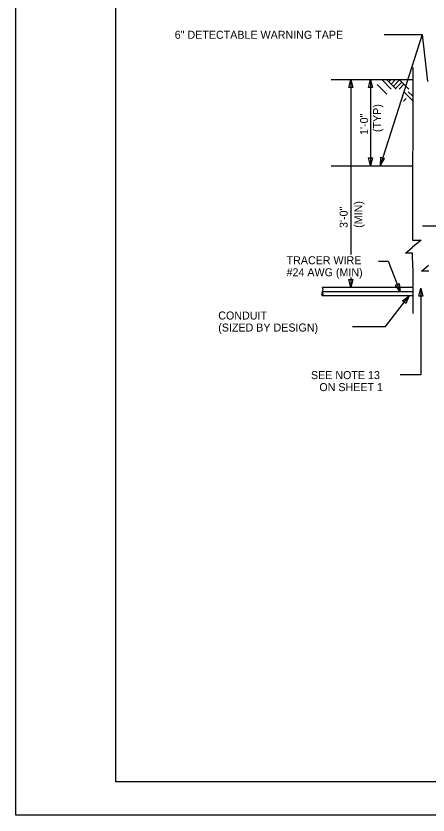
# Model space of a CAD drawing. Extents: x 1299104.8 to 1299141.6, y 239639.8 to 239661.8.
# Drawn here: x 1299104.8 to 1299110.98, y 239639.8 to 239651.78 of the extents above; entities that cross this region are included whole.
import ezdxf

# ---------------------------------------------------------------- set-up
doc = ezdxf.new("R2010")
doc.units = 0
for name, color, linetype in [('DIM TXT', 7, 'Continuous'), ('GS_plotshape_p', 7, 'Continuous'), ('Level 1', 7, 'Continuous')]:
    doc.layers.add(name, color=color, linetype=linetype)

msp = doc.modelspace()

# ---------------------------------------------------------------- linework, layer by layer
at = {"layer": 'DIM TXT'}
for p, q in [((1299110.897, 239651.5), (1299110.266, 239649.532)), ((1299110.755, 239651.005), (1299110.752, 239648.496)), ((1299109.532, 239650.823), (1299110.753, 239650.823)), ((1299109.825, 239650.823), (1299109.825, 239648.201)), ((1299110.123, 239650.823), (1299110.123, 239649.532)), ((1299110.433, 239650.68), (1299110.289, 239650.823)), ((1299110.504, 239650.681), (1299110.36, 239650.823)), ((1299110.429, 239650.823), (1299110.395, 239650.789)), ((1299110.497, 239650.823), (1299110.429, 239650.755)), ((1299110.558, 239650.818), (1299110.462, 239650.721)), ((1299110.696, 239650.681), (1299110.553, 239650.823)), ((1299110.366, 239650.602), (1299110.22, 239650.747)), ((1299110.593, 239650.783), (1299110.498, 239650.687)), ((1299110.623, 239650.754), (1299110.551, 239650.681)), ((1299110.753, 239650.509), (1299110.621, 239650.641)), ((1299110.754, 239650.573), (1299110.685, 239650.641)), ((1299110.657, 239650.538), (1299110.616, 239650.497)), ((1299109.532, 239649.532), (1299110.753, 239649.532)), ((1299110.752, 239648.678), (1299110.753, 239648.417)), ((1299120.075, 239648.627), (1299110.902, 239648.627)), ((1299110.753, 239648.417), (1299110.879, 239648.417)), ((1299110.879, 239648.417), (1299110.753, 239648.313)), ((1299110.644, 239648.222), (1299110.753, 239648.313)), ((1299110.753, 239648.222), (1299110.644, 239648.222)), ((1299110.754, 239648.004), (1299110.753, 239648.222)), ((1299110.754, 239648.004), (1299110.754, 239647.318)), ((1299110.885, 239647.952), (1299110.994, 239648.042)), ((1299110.995, 239647.952), (1299110.885, 239647.952)), ((1299109.825, 239647.858), (1299109.825, 239647.704)), ((1299110.754, 239647.706), (1299109.399, 239647.706)), ((1299110.754, 239647.642), (1299109.399, 239647.642)), ((1299110.754, 239647.581), (1299109.399, 239647.581))]:
    msp.add_line(p, q, dxfattribs=at)
for points in [[(1299110.325, 239651.5), (1299110.897, 239651.5), (1299110.976, 239650.793)], [(1299110.24, 239648.103), (1299110.385, 239648.103), (1299110.568, 239647.642)], [(1299110.874, 239647.698), (1299110.874, 239646.4), (1299110.564, 239646.4)], [(1299109.853, 239647.121), (1299110.347, 239647.121), (1299110.701, 239647.581)]]:
    msp.add_lwpolyline(points, dxfattribs=at)
for points in [[(1299109.797, 239650.705), (1299109.826, 239650.825), (1299109.857, 239650.706)], [(1299110.093, 239650.705), (1299110.122, 239650.825), (1299110.153, 239650.706)], [(1299110.152, 239649.652), (1299110.123, 239649.532), (1299110.092, 239649.652)], [(1299110.272, 239649.655), (1299110.266, 239649.532), (1299110.33, 239649.638)], [(1299109.854, 239647.827), (1299109.825, 239647.707), (1299109.794, 239647.827)], [(1299110.549, 239647.765), (1299110.568, 239647.643), (1299110.494, 239647.742)], [(1299110.845, 239647.578), (1299110.874, 239647.698), (1299110.905, 239647.578)], [(1299110.602, 239647.505), (1299110.7, 239647.581), (1299110.649, 239647.468)]]:
    msp.add_lwpolyline(points, close=True, dxfattribs=at)
for centre, start, end in [((1299109.366, 239647.675), 316.3972, 43.6028), ((1299109.432, 239647.612), 136.3972, 223.6028), ((1299109.366, 239647.612), 316.3972, 43.6028)]:
    msp.add_arc(centre, 0.0455, start, end, dxfattribs=at)
at = {"layer": 'GS_plotshape_p'}
msp.add_lwpolyline([(1299104.802, 239661.801), (1299138.802, 239661.801), (1299138.802, 239639.801), (1299104.802, 239639.801)], close=True, dxfattribs=at)
at = {"layer": 'Level 1'}
msp.add_lwpolyline([(1299138.302, 239640.301), (1299106.302, 239640.301), (1299106.302, 239661.301), (1299138.302, 239661.301)], close=True, dxfattribs=at)

# ---------------------------------------------------------------- texts
at = {"layer": 'DIM TXT'}
for s, p in [('6" DETECTABLE WARNING TAPE', (1299107.184, 239651.434)), ('TRACER WIRE', (1299108.862, 239648.055)), ('#24 AWG (MIN)', (1299108.862, 239647.875)), ('CONDUIT ', (1299107.837, 239647.227)), ('(SIZED BY DESIGN)', (1299107.837, 239647.047)), ('SEE NOTE 13', (1299109.228, 239646.334)), ('ON SHEET 1', (1299109.354, 239646.154))]:
    msp.add_text(s, height=0.12, dxfattribs=at).set_placement(p)
for s, p in [('(TYP)', (1299110.28, 239650.036)), ('1\'-0"', (1299110.085, 239649.993)), ('3\'-0"', (1299109.778, 239648.599)), ('(MIN)', (1299109.997, 239648.601))]:
    msp.add_text(s, height=0.12, rotation=90, dxfattribs=at).set_placement(p)

doc.saveas('drawing.dxf')
